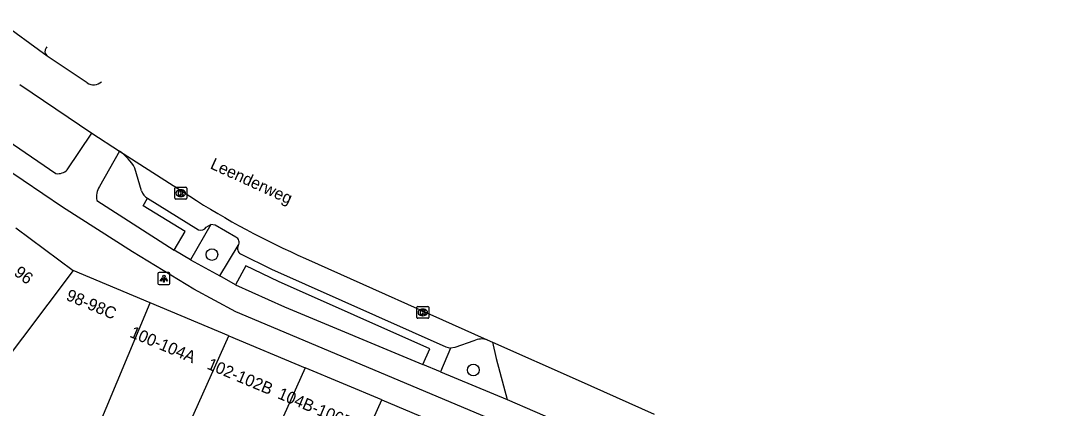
# Model space of a CAD drawing. Extents: x 161845 to 162341, y 381620 to 382158.
# Drawn here: x 162150.7 to 162238.1, y 381818.8 to 381851.4 of the extents above; entities that cross this region are included whole.
import ezdxf

# ---------------------------------------------------------------- set-up
doc = ezdxf.new("R2010")
doc.units = 0
for name, color, linetype in [('IMGEO_Boom', 7, 'Continuous'), ('IMGEO_Kolk', 7, 'Continuous'), ('IMGEO_Lichtpunt', 7, 'Continuous'), ('IMGEO_Openbare_ruimte_label', 7, 'Continuous'), ('IMGEO_Pand', 7, 'Continuous'), ('IMGEO_Pand_nummerreeks', 7, 'Continuous'), ('IMGEO_Parkeervlak_open', 7, 'Continuous'), ('IMGEO_Rijbaan_lokaal_gesloten', 7, 'Continuous'), ('IMGEO_Rijbaan_lokaal_open', 7, 'Continuous'), ('IMGEO_Voetpad_gesloten', 7, 'Continuous'), ('IMGEO_Voetpad_open', 7, 'Continuous')]:
    doc.layers.add(name, color=color, linetype=linetype)

msp = doc.modelspace()

# ---------------------------------------------------------------- linework, layer by layer
at = {"layer": 'IMGEO_Boom'}
for centre in [(162166.756, 381831.718), (162188.73, 381822.016)]:
    msp.add_circle(centre, 0.489, dxfattribs=at)
at = {"layer": 'IMGEO_Kolk'}
for p, q in [((162163.633, 381836.451), (162163.633, 381837.303)), ((162163.708, 381837.377), (162164.56, 381837.377)), ((162164.121, 381837.157), (162164.146, 381837.157)), ((162164.634, 381837.303), (162164.634, 381836.451)), ((162164.56, 381836.377), (162163.708, 381836.377)), ((162164.144, 381836.597), (162164.119, 381836.597)), ((162183.98, 381826.435), (162183.98, 381827.287)), ((162184.055, 381827.361), (162184.907, 381827.361)), ((162184.491, 381826.581), (162184.466, 381826.581)), ((162184.468, 381827.141), (162184.493, 381827.141)), ((162184.981, 381827.287), (162184.981, 381826.435)), ((162184.907, 381826.361), (162184.055, 381826.361))]:
    msp.add_line(p, q, dxfattribs=at)
for points in [[(162163.633, 381836.451), (162163.633, 381837.303)], [(162163.708, 381837.377), (162164.56, 381837.377)], [(162163.954, 381837.077), (162164.077, 381837.077), (162164.077, 381836.926), (162164.207, 381837.077), (162164.371, 381837.077), (162164.225, 381836.926), (162164.378, 381836.677), (162164.226, 381836.677), (162164.141, 381836.841), (162164.077, 381836.774), (162164.077, 381836.677), (162163.954, 381836.677), (162163.954, 381837.077)], [(162164.634, 381837.303), (162164.634, 381836.451)], [(162164.56, 381836.377), (162163.708, 381836.377)], [(162183.98, 381826.435), (162183.98, 381827.287)], [(162184.055, 381827.361), (162184.907, 381827.361)], [(162184.301, 381827.061), (162184.424, 381827.061), (162184.424, 381826.91), (162184.554, 381827.061), (162184.718, 381827.061), (162184.572, 381826.91), (162184.725, 381826.661), (162184.573, 381826.661), (162184.488, 381826.825), (162184.424, 381826.758), (162184.424, 381826.661), (162184.301, 381826.661), (162184.301, 381827.061)], [(162184.981, 381827.287), (162184.981, 381826.435)], [(162184.907, 381826.361), (162184.055, 381826.361)]]:
    msp.add_lwpolyline(points, dxfattribs=at)
for centre, start, end in [((162163.71, 381837.301), 91.55205, 178.44795), ((162163.71, 381837.301), 91.55205, 178.44795), ((162164.558, 381837.301), 1.55205, 88.44795), ((162164.558, 381837.301), 1.55205, 88.44795), ((162163.71, 381836.453), 181.55205, 268.44795), ((162163.71, 381836.453), 181.55205, 268.44795), ((162164.558, 381836.453), 271.55205, 358.44795), ((162164.558, 381836.453), 271.55205, 358.44795), ((162184.057, 381827.285), 91.55205, 178.44795), ((162184.057, 381827.285), 91.55205, 178.44795), ((162184.905, 381827.285), 1.55205, 88.44795), ((162184.905, 381827.285), 1.55205, 88.44795), ((162184.057, 381826.437), 181.55205, 268.44795), ((162184.057, 381826.437), 181.55205, 268.44795), ((162184.905, 381826.437), 271.55205, 358.44795), ((162184.905, 381826.437), 271.55205, 358.44795)]:
    msp.add_arc(centre, 0.0765, start, end, dxfattribs=at)
for centre, major_axis, ratio, start_param, end_param in [((162164.12, 381836.877), (-0.387, 0.002), 0.722429, 4.712389, 7.853982), ((162164.145, 381836.877), (-0.39, 0.002), 0.717154, 1.570796, 4.712389), ((162184.467, 381826.861), (-0.387, 0.002), 0.722429, 4.712389, 7.853982), ((162184.492, 381826.861), (-0.39, 0.002), 0.717154, 1.570796, 4.712389)]:
    msp.add_ellipse(centre, major_axis=major_axis, ratio=ratio, start_param=start_param, end_param=end_param, dxfattribs=at)
at = {"layer": 'IMGEO_Lichtpunt'}
for p, q in [((162162.22, 381830.104), (162162.22, 381829.297)), ((162162.22, 381830.104), (162162.22, 381829.297)), ((162163.122, 381830.199), (162162.314, 381830.199)), ((162163.122, 381830.199), (162162.314, 381830.199)), ((162163.216, 381829.297), (162163.216, 381830.104)), ((162163.216, 381829.297), (162163.216, 381830.104)), ((162162.314, 381829.203), (162163.122, 381829.203)), ((162162.314, 381829.203), (162163.122, 381829.203))]:
    msp.add_line(p, q, dxfattribs=at)
for points in [[(162162.594, 381829.768), (162162.633, 381829.74), (162162.445, 381829.478), (162162.407, 381829.505), (162162.594, 381829.768)], [(162162.696, 381829.72), (162162.743, 381829.72), (162162.743, 381829.398), (162162.696, 381829.398), (162162.696, 381829.72)], [(162162.806, 381829.74), (162162.844, 381829.767), (162163.031, 381829.505), (162162.992, 381829.477), (162162.806, 381829.74)]]:
    msp.add_lwpolyline(points, dxfattribs=at)
msp.add_circle((162162.719, 381829.902), 0.0994, dxfattribs=at)
for centre, start, end in [((162162.314, 381830.104), 90, 180), ((162162.314, 381830.104), 90, 180), ((162163.122, 381830.104), 0, 90), ((162163.122, 381830.104), 0, 90), ((162162.314, 381829.297), 180, 270), ((162162.314, 381829.297), 180, 270), ((162163.122, 381829.297), 270, 0), ((162163.122, 381829.297), 270, 360)]:
    msp.add_arc(centre, 0.0946, start, end, dxfattribs=at)
at = {"layer": 'IMGEO_Pand'}
for points in [[(162150.263, 381833.955), (162155.076, 381830.366)], [(162155.076, 381830.366), (162146.531, 381819.056)], [(162161.549, 381827.655), (162155.076, 381830.366)], [(162153.095, 381807.419), (162161.549, 381827.655)], [(162168.182, 381824.878), (162161.549, 381827.655)], [(162162.716, 381812.696), (162168.182, 381824.878)], [(162168.182, 381824.878), (162174.599, 381822.191)], [(162174.599, 381822.191), (162169.133, 381810.009), (162167.915, 381810.519)], [(162181.034, 381819.497), (162174.599, 381822.191)], [(162175.567, 381807.313), (162181.034, 381819.497)], [(162181.034, 381819.497), (162188.075, 381816.549), (162188.305, 381815.945)]]:
    msp.add_lwpolyline(points, dxfattribs=at)
at = {"layer": 'IMGEO_Parkeervlak_open'}
for points in [[(162160.832, 381837.072), (162160.272, 381838.989)], [(162168.758, 381833.193), (162167.02, 381834.201), (162166.661, 381834.249)], [(162188.774, 381824.481), (162187.175, 381823.914), (162186.818, 381823.858)]]:
    msp.add_lwpolyline(points, dxfattribs=at)
for centre, radius, start, end in [((162156.493, 381836.831), 4.352, 29.72635, 55.04731), ((162161.977, 381837.492), 1.22, 200.14214, 238.23411), ((162168.54, 381832.74), 0.503, 328.24511, 64.36108), ((162189.45, 381822.955), 1.669, 74.19309, 113.89894)]:
    msp.add_arc(centre, radius, start, end, dxfattribs=at)
at = {"layer": 'IMGEO_Rijbaan_lokaal_gesloten'}
for points in [[(162152.909, 381848.404), (162148.821, 381851.365)], [(162156.265, 381846.145), (162152.909, 381848.404)], [(162150.594, 381846.009), (162156.657, 381841.909)], [(162156.657, 381841.909), (162158.986, 381840.398)], [(162158.986, 381840.398), (162164.889, 381836.622)], [(162174.607, 381831.399), (162189.905, 381824.561)], [(162189.905, 381824.561), (162190.345, 381824.364)]]:
    msp.add_lwpolyline(points, dxfattribs=at)
for centre, radius, start, end in [((162156.805, 381847.021), 1.029, 238.34293, 310.5487), ((162201.636, 381893.343), 67.584, 237.06213, 246.4257)]:
    msp.add_arc(centre, radius, start, end, dxfattribs=at)
at = {"layer": 'IMGEO_Rijbaan_lokaal_open'}
for points in [[(162190.345, 381824.364), (162197.539, 381821.152), (162203.924, 381818.301)], [(162190.345, 381824.364), (162190.643, 381822.973), (162191.564, 381819.539)], [(162191.564, 381819.539), (162200.882, 381815.518)]]:
    msp.add_lwpolyline(points, dxfattribs=at)
at = {"layer": 'IMGEO_Voetpad_gesloten'}
for points in [[(162289.497, 381752.523), (162284.268, 381764.473), (162282.076, 381768.974), (162280.091, 381772.447), (162277.759, 381775.733), (162275.072, 381778.709), (162271.828, 381781.089), (162266.754, 381783.434), (162197.313, 381814.891), (162168.761, 381826.912), (162165.238, 381828.801), (162160.086, 381831.935), (162154.18, 381835.7), (162147.552, 381840.181), (162140.263, 381845.513), (162134.882, 381849.978)], [(162147.999, 381842.366), (162153.639, 381838.523)], [(162154.592, 381838.844), (162156.657, 381841.909)], [(162158.986, 381840.398), (162157.312, 381837.428)], [(162157.069, 381836.267), (162163.589, 381832.092)], [(162164.958, 381831.269), (162163.589, 381832.092)], [(162164.958, 381831.269), (162167.418, 381829.919)], [(162168.74, 381829.184), (162167.418, 381829.919)], [(162168.74, 381829.184), (162172.861, 381827.333), (162184.486, 381822.474)], [(162185.978, 381821.85), (162184.486, 381822.474)], [(162185.978, 381821.85), (162191.564, 381819.539)]]:
    msp.add_lwpolyline(points, dxfattribs=at)
for centre, radius, start, end in [((162153.778, 381839.685), 1.17, 263.16843, 314.06182), ((162158.528, 381836.568), 1.489, 144.71412, 191.6429)]:
    msp.add_arc(centre, radius, start, end, dxfattribs=at)
at = {"layer": 'IMGEO_Voetpad_open'}
for points in [[(162152.862, 381849.169), (162152.812, 381849.099)], [(162163.589, 381832.092), (162164.515, 381833.671), (162160.982, 381835.828), (162161.335, 381836.455)], [(162161.335, 381836.455), (162165.622, 381833.804)], [(162166.661, 381834.249), (162164.958, 381831.269)], [(162166.28, 381834.01), (162166.661, 381834.249)], [(162167.418, 381829.919), (162168.968, 381832.475)], [(162169.166, 381831.776), (162171.748, 381830.494), (162186.408, 381823.952), (162186.818, 381823.858)], [(162184.486, 381822.474), (162185.071, 381823.796), (162172.352, 381829.469), (162169.605, 381830.784), (162168.74, 381829.184)], [(162186.818, 381823.858), (162185.978, 381821.85)]]:
    msp.add_lwpolyline(points, dxfattribs=at)
for centre, radius, start, end in [((162153.224, 381848.802), 0.508, 144.23792, 231.65278), ((162165.826, 381834.307), 0.542, 247.91666, 326.85087), ((162169.405, 381832.221), 0.505, 149.87161, 241.75919)]:
    msp.add_arc(centre, radius, start, end, dxfattribs=at)

# ---------------------------------------------------------------- texts
at = {"layer": 'IMGEO_Openbare_ruimte_label'}
msp.add_text('Leenderweg', height=1, rotation=335.409, dxfattribs=at).set_placement((162166.535, 381838.982))
at = {"layer": 'IMGEO_Pand_nummerreeks'}
for s, rotation, p in [('96', 323.02895, (162150.045, 381830.048)), ('98-98C', 337.27649, (162154.416, 381827.932)), ('100-104A', 337.24212, (162159.776, 381824.819)), ('102-102B', 337.26503, (162166.269, 381822.145)), ('104B-106B', 337.21347, (162172.205, 381819.663))]:
    msp.add_text(s, height=1, rotation=rotation, dxfattribs=at).set_placement(p)

doc.saveas('drawing.dxf')
